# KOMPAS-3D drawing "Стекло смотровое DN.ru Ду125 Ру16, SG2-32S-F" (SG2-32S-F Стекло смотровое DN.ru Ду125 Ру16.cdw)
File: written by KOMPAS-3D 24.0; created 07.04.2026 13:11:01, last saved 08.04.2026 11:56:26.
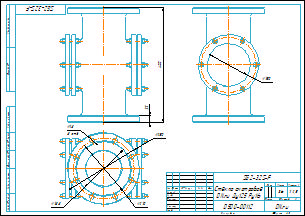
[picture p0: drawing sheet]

Document properties: Автор: Main; Форматы листов документа: A3; Полное имя файла: SG2-32S-F Стекло смотровое DN.ru Ду125 Ру16.m3d; Масса: 36; Наименование: Стекло смотровое DN.ru Ду125 Ру16; Количество листов документа: 1; Примечание: D500-00112

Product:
- Body: Тело 1  | qty 1
    Масса: 38.267558
- Part/product: Стекло смотровое DN.ru Ду125 Ру16  | designation SG2-32S-F
    Масса: 36
    Раздел спецификации: Прочие изделия
    Примечание: D500-00112

Referenced files in D:\DN.ru Аутсерс\Стекло смотровое DN.ru\Стекло смотровое DN.ru SG2-34G-F тип В ГОСТ 21836-2021 Ду100 Ру16, углеродистая сталь, фланцевое\: SG2-34G-F тип ВСтекло смотровое DN.ru Ду100 Ру16.cdw
Referenced files in D:\DN.ru Аутсерс\Стекло смотровое DN.ru\SG2-32S-F Стекло смотровое DN.ru Ду125 Ру16\: SG2-32S-F Стекло смотровое DN.ru Ду125 Ру16.m3d
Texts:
  Стекло смотровое
  DN.ru Ду125 Ру16
  SG2-32S-F
  Стекло смотровое DN.ru Ду125 Ру16
  SG2-32S-F Стекло смотровое DN.ru Ду125 Ру16
Dimensions and other numbers on the sheet: 1:2,5; 0; 1; 2; 36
